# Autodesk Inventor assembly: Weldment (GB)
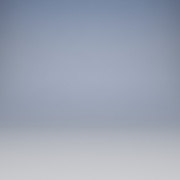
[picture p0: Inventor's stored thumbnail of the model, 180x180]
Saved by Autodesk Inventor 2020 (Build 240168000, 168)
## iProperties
Length Units: 11269
Angle Units: 11283
Time Units: 11279
Mass Units: 11290
Length Display Precision: 3
Angle Display Precision: 2
Part Number: Weldment (GB)
Document SubType Name: Weldment
Created: 2002-06
Designer: smithga
Created: 2002-08
Weld Material: Welded Aluminum-6061
Manager: www.cadconsulting.pl
Company: Fabian Stasiak CAD Consulting
Control State: 0
Master: False
Shininess: 64.0
Angle Units: 11279
Time Units: 11290
Mass Units: 11283
Compacted: True
Density: 0.0
Volumn: 0.0
Area: 0.0
PropertySet Name: Model Information
Author: F.Stasiak
Subject: Zbiór ćwiczeń. Autodesk Inventor 2020. Kurs podstawowy
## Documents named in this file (1)
- M:\AUTOBUILD\M24_168_RTM\Application\App\Templates\en-US\Metric\Weldment (GB).iam
